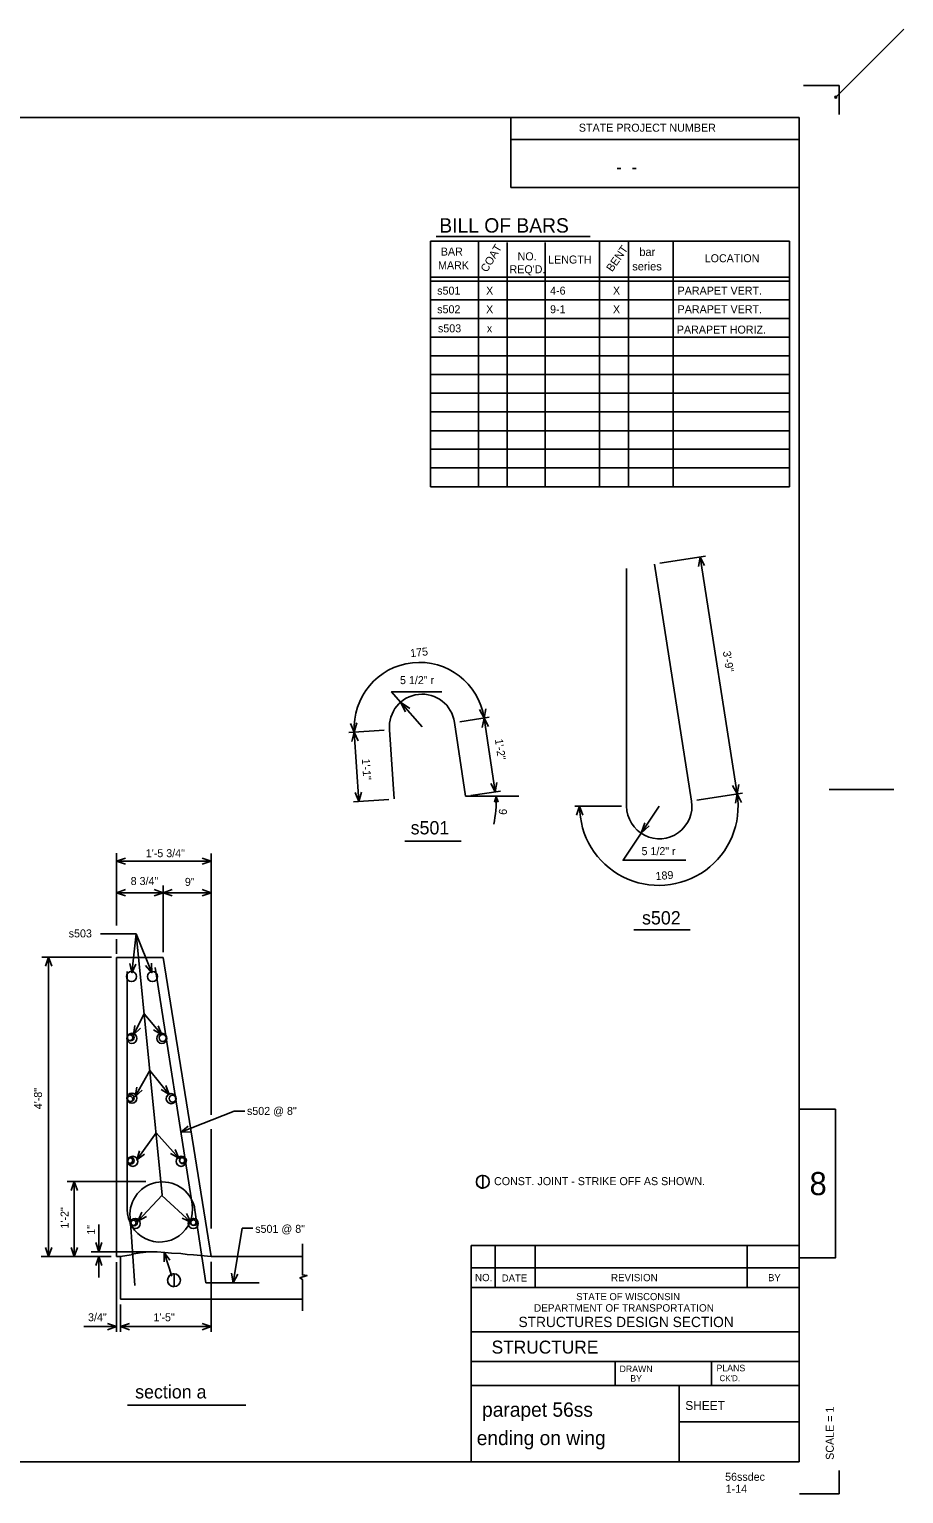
# Model space of a CAD drawing. Extents: x -38.4 to -2.2, y 84.9 to 109.4.
# Drawn here: x -15.84 to -2.17, y 85.97 to 108.85 of the extents above; entities that cross this region are included whole.
import ezdxf

# ---------------------------------------------------------------- set-up
doc = ezdxf.new("R2010")
doc.units = 0
for name, color, linetype in [('Default', 7, 'Continuous'), ('Level 1', 7, 'Continuous'), ('Level 2', 7, 'Continuous'), ('Level 37', 7, 'Continuous'), ('Level 49', 7, 'Continuous')]:
    doc.layers.add(name, color=color, linetype=linetype)

msp = doc.modelspace()

# ---------------------------------------------------------------- linework, layer by layer
at = {"layer": 'Default'}
for p, q in [((-14.473, 94.846), (-14.473, 95.978)), ((-14.473, 95.851), (-12.994, 95.851)), ((-12.994, 94.526), (-12.994, 95.97)), ((-13.744, 94.428), (-13.744, 95.471)), ((-14.473, 95.358), (-13.744, 95.358)), ((-13.744, 95.358), (-12.994, 95.358)), ((-14.168, 94.719), (-14.722, 94.719)), ((-14.232, 94.11), (-14.168, 94.719)), ((-14.168, 94.719), (-13.759, 90.637)), ((-14.168, 94.719), (-13.919, 94.11)), ((-12.994, 91.891), (-12.994, 94.809)), ((-14.473, 94.428), (-14.473, 94.634)), ((-14.473, 94.407), (-14.473, 94.617)), ((-14.55, 94.355), (-15.639, 94.355)), ((-15.533, 89.678), (-15.533, 94.355)), ((-14.473, 94.345), (-13.744, 94.345)), ((-14.473, 94.345), (-14.473, 89.678)), ((-12.994, 89.678), (-13.744, 94.345)), ((-14.304, 94.126), (-14.304, 90.412)), ((-13.291, 90.492), (-13.869, 94.193)), ((-14.206, 93.138), (-14.043, 93.469)), ((-14.043, 93.469), (-13.767, 93.138)), ((-14.181, 92.175), (-13.954, 92.581)), ((-13.954, 92.581), (-13.649, 92.209)), ((-12.633, 91.949), (-13.467, 91.617)), ((-12.466, 91.949), (-12.633, 91.949)), ((-14.156, 91.186), (-13.856, 91.609)), ((-13.856, 91.609), (-13.497, 91.212)), ((-12.994, 90.113), (-12.994, 91.664)), ((-14.017, 90.847), (-15.245, 90.847)), ((-15.133, 89.678), (-15.133, 90.847)), ((-8.748, 90.743), (-8.748, 90.943)), ((-8.748, 90.743), (-8.748, 90.943)), ((-13.759, 90.637), (-14.139, 90.231)), ((-13.311, 90.214), (-13.763, 90.632)), ((-13.078, 89.267), (-13.248, 90.4)), ((-14.75, 89.752), (-14.75, 90.178)), ((-14.189, 89.226), (-14.262, 90.286)), ((-12.509, 90.121), (-12.652, 89.267)), ((-12.342, 90.121), (-12.509, 90.121)), ((-14.557, 89.678), (-15.649, 89.678)), ((-15.213, 89.678), (-15.05, 89.678)), ((-13.943, 89.752), (-14.871, 89.752)), ((-14.75, 89.349), (-14.75, 89.678)), ((-14.473, 89.678), (-14.411, 89.678)), ((-14.411, 89.678), (-14.411, 89.011)), ((-13.611, 89.371), (-13.727, 89.741)), ((-11.568, 89.678), (-12.994, 89.678)), ((-14.473, 89.586), (-14.473, 88.498)), ((-12.994, 89.595), (-12.994, 88.498)), ((-13.573, 89.204), (-13.573, 89.405)), ((-13.078, 89.267), (-12.244, 89.267)), ((-14.411, 89.011), (-11.568, 89.011)), ((-14.411, 88.928), (-14.411, 88.498)), ((-14.473, 88.581), (-14.982, 88.581)), ((-14.411, 88.581), (-12.994, 88.581)), ((-14.302, 87.356), (-12.451, 87.356))]:
    msp.add_line(p, q, dxfattribs=at)
for points in [[(-14.333, 95.803), (-14.473, 95.851), (-14.333, 95.9)], [(-13.135, 95.9), (-12.994, 95.851), (-13.135, 95.803)], [(-14.333, 95.309), (-14.473, 95.358), (-14.333, 95.407)], [(-13.885, 95.407), (-13.744, 95.358), (-13.885, 95.309)], [(-13.603, 95.309), (-13.744, 95.358), (-13.603, 95.407)], [(-13.135, 95.407), (-12.994, 95.358), (-13.135, 95.309)], [(-15.582, 94.214), (-15.533, 94.355), (-15.484, 94.214)], [(-14.169, 94.245), (-14.232, 94.11), (-14.265, 94.256)], [(-13.927, 94.259), (-13.919, 94.11), (-14.018, 94.222)], [(-14.1, 93.243), (-14.206, 93.138), (-14.187, 93.286)], [(-13.82, 93.278), (-13.767, 93.138), (-13.895, 93.216)], [(-14.07, 92.274), (-14.181, 92.175), (-14.155, 92.322)], [(-13.7, 92.349), (-13.649, 92.209), (-13.776, 92.287)], [(-13.318, 91.624), (-13.467, 91.617), (-13.354, 91.714)], [(-14.035, 91.273), (-14.156, 91.186), (-14.114, 91.329)], [(-13.555, 91.349), (-13.497, 91.212), (-13.627, 91.284)], [(-15.182, 90.706), (-15.133, 90.847), (-15.084, 90.706)], [(-14.007, 90.301), (-14.139, 90.231), (-14.078, 90.367)], [(-13.381, 90.346), (-13.311, 90.214), (-13.447, 90.274)], [(-13.355, 90.297), (-13.311, 90.214), (-13.396, 90.252)], [(-15.484, 89.819), (-15.533, 89.678), (-15.582, 89.819)], [(-15.084, 89.819), (-15.133, 89.678), (-15.182, 89.819)], [(-14.701, 89.893), (-14.75, 89.752), (-14.798, 89.893)], [(-14.798, 89.537), (-14.75, 89.678), (-14.701, 89.537)], [(-14.411, 89.678), (-14.245, 89.7), (-14.233, 89.712), (-14.101, 89.734), (-13.966, 89.752), (-13.837, 89.749), (-13.717, 89.737), (-13.616, 89.728), (-13.469, 89.725), (-13.371, 89.71), (-13.269, 89.7), (-12.994, 89.678)], [(-13.731, 89.592), (-13.727, 89.741), (-13.638, 89.621)], [(-11.568, 88.826), (-11.568, 89.319), (-11.609, 89.341), (-11.497, 89.382), (-11.568, 89.388), (-11.568, 89.874)], [(-12.58, 89.398), (-12.652, 89.267), (-12.676, 89.414)], [(-14.614, 88.63), (-14.473, 88.581), (-14.614, 88.533)], [(-14.27, 88.533), (-14.411, 88.581), (-14.27, 88.63)], [(-13.135, 88.63), (-12.994, 88.581), (-13.135, 88.533)]]:
    msp.add_lwpolyline(points, dxfattribs=at)
for points in [[(-8.748, 90.744), (-8.748, 90.943), (-8.748, 90.944), (-8.767, 90.943), (-8.789, 90.937), (-8.807, 90.927), (-8.826, 90.91), (-8.837, 90.895), (-8.846, 90.874), (-8.851, 90.849), (-8.849, 90.825), (-8.844, 90.807), (-8.831, 90.783), (-8.818, 90.77), (-8.802, 90.757), (-8.785, 90.75), (-8.77, 90.746), (-8.762, 90.744)], [(-8.748, 90.744), (-8.748, 90.943), (-8.748, 90.944), (-8.767, 90.943), (-8.789, 90.937), (-8.807, 90.927), (-8.826, 90.91), (-8.837, 90.895), (-8.846, 90.874), (-8.851, 90.849), (-8.849, 90.825), (-8.844, 90.807), (-8.831, 90.783), (-8.818, 90.77), (-8.802, 90.757), (-8.785, 90.75), (-8.77, 90.746), (-8.762, 90.744)], [(-13.573, 89.205), (-13.573, 89.405), (-13.573, 89.405), (-13.592, 89.404), (-13.614, 89.399), (-13.632, 89.388), (-13.651, 89.372), (-13.662, 89.356), (-13.671, 89.335), (-13.676, 89.31), (-13.673, 89.286), (-13.669, 89.269), (-13.656, 89.245), (-13.643, 89.232), (-13.627, 89.219), (-13.61, 89.212), (-13.595, 89.207), (-13.586, 89.206)]]:
    msp.add_lwpolyline(points, close=True, dxfattribs=at)
for centre, radius in [((-14.239, 94.049), 0.0788), ((-13.91, 94.049), 0.0788), ((-14.232, 93.084), 0.0788), ((-14.253, 93.099), 0.0539), ((-14.262, 93.095), 0.0417), ((-13.764, 93.084), 0.0788), ((-13.752, 93.091), 0.0539), ((-14.232, 92.15), 0.0788), ((-14.253, 92.151), 0.0539), ((-13.618, 92.142), 0.0788), ((-13.598, 92.143), 0.0539), ((-14.262, 92.137), 0.0417), ((-14.253, 91.172), 0.0539), ((-14.262, 91.175), 0.0417), ((-14.217, 91.163), 0.0788), ((-13.464, 91.163), 0.0788), ((-13.436, 91.18), 0.0539), ((-13.447, 91.178), 0.0417), ((-8.75, 90.844), 0.1), ((-8.75, 90.844), 0.1), ((-14.18, 90.192), 0.0788), ((-14.199, 90.209), 0.0539), ((-14.208, 90.203), 0.0417), ((-13.274, 90.192), 0.0788), ((-13.266, 90.217), 0.0539), ((-13.272, 90.206), 0.0417), ((-13.575, 89.306), 0.1)]:
    msp.add_circle(centre, radius, dxfattribs=at)
for centre, start, end in [((-13.753, 90.332), 7.615, 185.2003), ((-13.795, 90.412), 180, 9)]:
    msp.add_arc(centre, 0.51, start, end, dxfattribs=at)
at = {"layer": 'Level 1'}
for p, q in [((-3.184, 107.971), (-3.739, 107.971)), ((-3.184, 107.516), (-3.184, 107.971)), ((-3.809, 107.471), (-35.185, 107.471)), ((-8.315, 107.471), (-8.315, 106.375)), ((-3.809, 86.471), (-3.809, 107.471)), ((-8.315, 107.126), (-3.809, 107.126)), ((-8.315, 106.375), (-3.809, 106.375)), ((-5.489, 96.791), (-6.068, 100.492)), ((-5.985, 100.505), (-5.274, 100.616)), ((-5.356, 100.603), (-4.778, 96.902)), ((-6.503, 100.425), (-6.503, 96.711)), ((-9.699, 97.951), (-10.034, 98.336)), ((-9.02, 96.865), (-9.193, 98.019)), ((-9.111, 98.031), (-8.649, 98.1)), ((-8.731, 98.088), (-8.558, 96.934)), ((-10.29, 97.899), (-10.842, 97.861)), ((-10.685, 96.786), (-10.758, 97.867)), ((-10.133, 96.824), (-10.207, 97.905)), ((-10.217, 96.818), (-10.768, 96.781)), ((-9.02, 96.865), (-8.187, 96.865)), ((-8.938, 96.877), (-8.476, 96.946)), ((-5.407, 96.804), (-4.695, 96.915)), ((-6.586, 96.711), (-7.313, 96.711)), ((-5.993, 96.711), (-6.277, 96.287)), ((-9.97, 96.166), (-9.091, 96.166)), ((-6.392, 94.779), (-5.513, 94.779)), ((-8.934, 89.846), (-3.806, 89.846)), ((-8.934, 89.19), (-8.934, 89.846)), ((-8.555, 89.19), (-8.555, 89.846)), ((-7.93, 89.19), (-7.93, 89.846)), ((-4.618, 89.19), (-4.618, 89.846)), ((-8.934, 89.502), (-3.806, 89.502)), ((-8.934, 86.471), (-8.934, 89.19)), ((-8.934, 89.19), (-3.806, 89.19)), ((-8.934, 88.502), (-3.806, 88.502)), ((-8.934, 88.034), (-3.806, 88.034)), ((-6.683, 87.659), (-6.683, 88.034)), ((-5.176, 87.659), (-5.176, 88.034)), ((-8.934, 87.659), (-3.806, 87.659)), ((-5.684, 86.471), (-5.684, 87.659)), ((-5.683, 87.096), (-3.809, 87.096)), ((-35.185, 86.471), (-3.809, 86.471)), ((-3.184, 85.971), (-3.184, 86.334)), ((-3.802, 85.971), (-3.184, 85.971))]:
    msp.add_line(p, q, dxfattribs=at)
for points in [[(-5.382, 100.456), (-5.356, 100.603), (-5.286, 100.471)], [(-10.034, 98.336), (-10.175, 98.499), (-9.388, 98.499)], [(-9.956, 98.183), (-10.034, 98.336), (-9.893, 98.238)], [(-8.704, 98.234), (-8.731, 98.088), (-8.8, 98.22)], [(-10.719, 98.011), (-10.758, 97.867), (-10.817, 98.004)], [(-8.758, 97.941), (-8.731, 98.088), (-8.662, 97.956)], [(-10.797, 97.723), (-10.758, 97.867), (-10.7, 97.73)], [(-8.531, 97.081), (-8.558, 96.934), (-8.627, 97.066)], [(-4.751, 97.049), (-4.778, 96.902), (-4.847, 97.034)], [(-10.646, 96.93), (-10.685, 96.786), (-10.743, 96.924)], [(-4.804, 96.756), (-4.778, 96.902), (-4.708, 96.771)], [(-7.286, 96.57), (-7.238, 96.711), (-7.189, 96.57)], [(-6.15, 96.402), (-6.277, 96.287), (-6.219, 96.449)], [(-6.277, 96.287), (-6.558, 95.866), (-5.579, 95.866)]]:
    msp.add_lwpolyline(points, dxfattribs=at)
msp.add_lwpolyline([(-3.809, 91.976), (-3.242, 91.976), (-3.242, 89.654), (-3.809, 89.654)], close=True, dxfattribs=at)
for centre, radius, start, end in [((-9.74, 97.937), 1.02, 8.5231, 183.9058), ((-9.699, 97.951), 0.51, 7.615, 185.2003), ((-6, 96.711), 1.238, 180, 8.8807), ((-5.993, 96.711), 0.51, 180, 9)]:
    msp.add_arc(centre, radius, start, end, dxfattribs=at)
at = {"layer": 'Level 2'}
for p, q in [((-3.235, 107.786), (-2.175, 108.847)), ((-9.568, 105.536), (-8.343, 105.536)), ((-9.568, 105.536), (-9.568, 101.702)), ((-9.48, 105.608), (-7.072, 105.608)), ((-8.818, 105.536), (-8.818, 101.702)), ((-8.368, 105.519), (-8.368, 101.702)), ((-8.343, 105.536), (-7.775, 105.536)), ((-7.775, 105.536), (-5.775, 105.536)), ((-7.775, 105.519), (-7.775, 101.702)), ((-6.925, 105.536), (-6.925, 101.702)), ((-6.475, 105.536), (-6.475, 101.702)), ((-5.775, 105.536), (-3.958, 105.536)), ((-5.775, 105.536), (-5.775, 101.702)), ((-3.958, 105.536), (-3.958, 101.702)), ((-9.568, 104.973), (-7.775, 104.973)), ((-9.568, 104.911), (-7.775, 104.911)), ((-7.775, 104.973), (-5.775, 104.973)), ((-7.775, 104.911), (-5.775, 104.911)), ((-5.775, 104.973), (-3.958, 104.973)), ((-5.775, 104.911), (-3.958, 104.911)), ((-9.568, 104.619), (-7.775, 104.619)), ((-7.775, 104.619), (-5.775, 104.619)), ((-5.775, 104.619), (-3.958, 104.619)), ((-9.568, 104.327), (-7.775, 104.327)), ((-7.775, 104.327), (-5.775, 104.327)), ((-5.775, 104.327), (-3.958, 104.327)), ((-9.568, 104.036), (-7.775, 104.036)), ((-7.775, 104.036), (-5.775, 104.036)), ((-5.775, 104.036), (-3.958, 104.036)), ((-9.568, 103.744), (-7.775, 103.744)), ((-7.775, 103.744), (-5.775, 103.744)), ((-5.775, 103.744), (-3.958, 103.744)), ((-9.568, 103.452), (-7.775, 103.452)), ((-7.775, 103.452), (-5.775, 103.452)), ((-5.775, 103.452), (-3.958, 103.452)), ((-9.568, 103.161), (-7.775, 103.161)), ((-7.775, 103.161), (-5.775, 103.161)), ((-5.775, 103.161), (-3.958, 103.161)), ((-9.568, 102.869), (-7.775, 102.869)), ((-7.775, 102.869), (-5.775, 102.869)), ((-5.775, 102.869), (-3.958, 102.869)), ((-9.568, 102.577), (-7.775, 102.577)), ((-7.775, 102.577), (-5.775, 102.577)), ((-5.775, 102.577), (-3.958, 102.577)), ((-9.568, 102.286), (-7.775, 102.286)), ((-7.775, 102.286), (-5.775, 102.286)), ((-5.775, 102.286), (-3.958, 102.286)), ((-9.568, 101.994), (-7.775, 101.994)), ((-7.775, 101.994), (-5.775, 101.994)), ((-5.775, 101.994), (-3.958, 101.994)), ((-9.568, 101.702), (-7.775, 101.702)), ((-9.568, 101.702), (-7.775, 101.702)), ((-7.775, 101.702), (-3.958, 101.702)), ((-7.775, 101.702), (-3.958, 101.702))]:
    msp.add_line(p, q, dxfattribs=at)
msp.add_lwpolyline([(-8.57, 96.774), (-8.543, 96.863), (-8.509, 96.776)], dxfattribs=at)
msp.add_arc((-10.254, 96.793), 1.713, 347.6879, 2.3357, dxfattribs=at)
at = {"layer": 'Level 37'}
msp.add_line((-3.339, 96.971), (-2.329, 96.971), dxfattribs=at)
at = {"layer": 'Level 49'}
msp.add_circle((-3.236, 107.786), 0.0152, dxfattribs=at)

# ---------------------------------------------------------------- texts
at = {"layer": 'Default'}
for s, height, p in [('1\'-5 3/4"', 0.125, (-14.016, 95.914)), ('8 3/4"', 0.125, (-14.252, 95.479)), ('9"', 0.125, (-13.405, 95.466)), ('s503', 0.125, (-15.22, 94.661)), ('s502 @ 8"', 0.125, (-12.435, 91.888)), ('CONST. JOINT - STRIKE OFF AS SHOWN.', 0.125, (-8.575, 90.791)), ('CONST. JOINT - STRIKE OFF AS SHOWN.', 0.125, (-8.575, 90.791)), ('s501 @ 8"', 0.125, (-12.306, 90.046)), ('3/4"', 0.125, (-14.918, 88.665)), ('1\'-5"', 0.125, (-13.896, 88.665)), ('section a', 0.2083, (-14.182, 87.459)), ('56ssdec', 0.125, (-4.965, 86.173)), ('1-14', 0.125, (-4.956, 85.985))]:
    msp.add_text(s, height=height, dxfattribs=at).set_placement(p)
for s, p in [('4\'-8"', (-15.637, 91.977)), ('1\'-2"', (-15.222, 90.113)), ('1"', (-14.807, 90.016))]:
    msp.add_text(s, height=0.125, rotation=90, dxfattribs=at).set_placement(p)
at = {"layer": 'Level 1'}
for s, height, p in [('STATE PROJECT NUMBER', 0.12525, (-7.25, 107.247)), ('    -  -  ', 0.2023, (-6.969, 106.594)), ('5 1/2" r', 0.125, (-10.044, 98.618)), ('s501', 0.2083, (-9.878, 96.27)), ('5 1/2" r', 0.125, (-6.271, 95.946)), ('s502', 0.2083, (-6.263, 94.863)), ('8', 0.361, (-3.646, 90.635)), ('NO.', 0.1139, (-8.872, 89.291)), ('DATE', 0.1109, (-8.454, 89.286)), ('REVISION', 0.1142, (-6.748, 89.29)), ('BY', 0.1108, (-4.294, 89.29)), ('STATE OF WISCONSIN', 0.11076, (-7.291, 88.995)), ('DEPARTMENT OF TRANSPORTATION', 0.11643, (-7.951, 88.815)), ('STRUCTURES DESIGN SECTION', 0.1605, (-8.193, 88.574)), ('STRUCTURE', 0.2022, (-8.613, 88.16)), ('DRAWN', 0.1022, (-6.614, 87.871)), ('PLANS', 0.1023, (-5.099, 87.883)), ('BY', 0.102, (-6.446, 87.721)), ("CK'D.", 0.0927, (-5.052, 87.729)), (' parapet 56ss ', 0.22392, (-8.845, 87.173)), ('SHEET', 0.1387, (-5.587, 87.28)), ('ending on wing', 0.22392, (-8.845, 86.73))]:
    msp.add_text(s, height=height, dxfattribs=at).set_placement(p)
for s, rotation, p in [('175', 6.2145, (-9.879, 99.038)), ('3\'-9"', 278.8807, (-5.002, 99.126)), ('1\'-2"', 278.5231, (-8.563, 97.754)), ('1\'-1"', 273.9058, (-10.64, 97.449)), ('189', 4.4403, (-6.047, 95.556)), ('SCALE = 1        ', 90, (-3.267, 86.5))]:
    msp.add_text(s, height=0.125, rotation=rotation, dxfattribs=at).set_placement(p)
at = {"layer": 'Level 2'}
for s, height, p in [('BILL OF BARS', 0.225, (-9.43, 105.671)), ('BAR', 0.125, (-9.407, 105.312)), ('NO.', 0.125, (-8.207, 105.238)), ('LENGTH', 0.125, (-7.73, 105.188)), ('bar', 0.1294, (-6.305, 105.305)), ('LOCATION', 0.125, (-5.284, 105.208)), ('MARK', 0.125, (-9.45, 105.098)), ("REQ'D.", 0.125, (-8.334, 105.036)), ('series', 0.1294, (-6.416, 105.08)), ('s501', 0.125, (-9.463, 104.702)), ('X', 0.125, (-8.699, 104.702)), (' 4-6 ', 0.125, (-7.746, 104.702)), ('X', 0.125, (-6.717, 104.702)), ('PARAPET VERT.   ', 0.125, (-5.707, 104.702)), ('s502', 0.125, (-9.463, 104.411)), ('X', 0.125, (-8.699, 104.411)), (' 9-1 ', 0.125, (-7.746, 104.411)), ('X', 0.125, (-6.717, 104.411)), ('PARAPET VERT.   ', 0.125, (-5.707, 104.411)), ('s503', 0.125, (-9.451, 104.113)), ('x', 0.125, (-8.687, 104.113)), ('PARAPET HORIZ.  ', 0.125, (-5.719, 104.093))]:
    msp.add_text(s, height=height, dxfattribs=at).set_placement(p)
for s, rotation, p in [('COAT', 59.0083, (-8.687, 105.041)), ('BENT', 54.9994, (-6.73, 105.049)), ('9', 265.9161, (-8.496, 96.675))]:
    msp.add_text(s, height=0.125, rotation=rotation, dxfattribs=at).set_placement(p)

doc.saveas('drawing.dxf')
